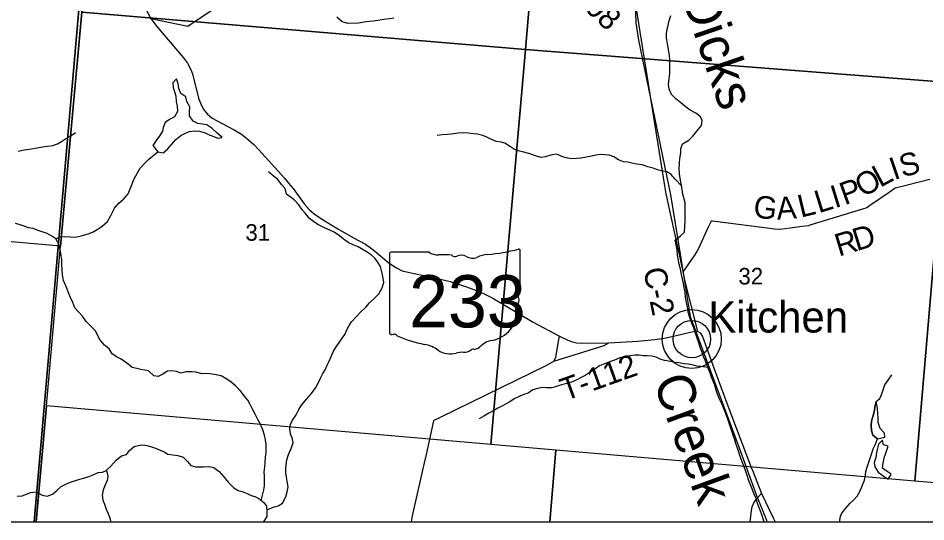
# Model space of a CAD drawing. Extents: x 0 to 42, y 0 to 22.
# Drawn here: x 4.786 to 5.931, y 14.1 to 14.736 of the extents above; entities that cross this region are included whole.
import ezdxf

# ---------------------------------------------------------------- set-up
doc = ezdxf.new("R2010")
doc.units = 0
for name, color, linetype in [('GM_X_County_Road', 7, 'Continuous'), ('GM_X_County_Road_Text', 7, 'Continuous'), ('GM_X_Major_River', 7, 'Continuous'), ('GM_X_Minor_Lake', 7, 'Continuous'), ('GM_X_Minor_River', 7, 'Continuous'), ('GM_X_Minor_River_Text', 7, 'Continuous'), ('GM_X_Rail_Line', 7, 'Continuous'), ('GM_X_Section', 7, 'Continuous'), ('GM_X_Section_Text', 7, 'Continuous'), ('GM_X_State_Location', 7, 'Continuous'), ('GM_X_State_Route', 7, 'Continuous'), ('GM_X_State_Shield', 7, 'Continuous'), ('GM_X_Township_Road', 7, 'Continuous'), ('GM_X_Township_Road_Text', 7, 'Continuous'), ('GM_X_Unincorporated', 7, 'Continuous'), ('GM_X_Unincorporated_Location', 7, 'Continuous'), ('GM_X_Unincorporated_Text', 7, 'Continuous'), ('SH_Cut_Line', 7, 'Continuous'), ('SH_Data', 7, 'Continuous')]:
    doc.layers.add(name, color=color, linetype=linetype)

msp = doc.modelspace()

# ---------------------------------------------------------------- linework, layer by layer
at = {"layer": 'GM_X_County_Road'}
for points in [[(5.6248, 14.416), (5.6235, 14.4219), (5.6031, 14.5142), (5.6015, 14.524), (5.5656, 14.7501), (5.5654, 14.7514)], [(5.6264, 14.4073), (5.6255, 14.4121), (5.6248, 14.416)], [(5.6433, 14.3404), (5.6265, 14.4068), (5.6264, 14.4073)], [(5.3009, 14.185), (5.3104, 14.2274), (5.3106, 14.2283), (5.3186, 14.2321), (5.4529, 14.2977), (5.4618, 14.3027), (5.4642, 14.3074), (5.4667, 14.323), (5.4686, 14.3345)], [(5.282, 14.1), (5.2836, 14.1074), (5.2986, 14.1746), (5.3009, 14.185)]]:
    msp.add_lwpolyline(points, dxfattribs=at)
at = {"layer": 'GM_X_Major_River'}
for points in [[(4.7848, 14.1324), (4.7912, 14.133), (4.7965, 14.1349), (4.8022, 14.1372), (4.8088, 14.1378), (4.8166, 14.1336), (4.8225, 14.1326), (4.8295, 14.1351), (4.8355, 14.1402), (4.8403, 14.1448), (4.8469, 14.148), (4.8522, 14.1501), (4.8585, 14.152), (4.864, 14.1539), (4.8702, 14.1556), (4.8753, 14.1572), (4.8814, 14.1596), (4.8871, 14.1623), (4.8924, 14.1629), (4.8971, 14.1648), (4.903, 14.1703), (4.9098, 14.1779), (4.9163, 14.1832), (4.9229, 14.1849), (4.9267, 14.19), (4.9326, 14.195), (4.9373, 14.1965), (4.9435, 14.1971), (4.9485, 14.1963), (4.9532, 14.195)], [(4.9532, 14.195), (4.9595, 14.1929), (4.9652, 14.1906), (4.9701, 14.1882), (4.975, 14.1855), (4.9813, 14.1844), (4.9875, 14.1838), (4.9942, 14.1816), (4.9997, 14.1761), (5.004, 14.1713), (5.0097, 14.1694), (5.0148, 14.1696), (5.0199, 14.1694), (5.0266, 14.1698), (5.033, 14.1687), (5.0396, 14.1634), (5.0453, 14.1567), (5.051, 14.1503), (5.058, 14.1431), (5.0635, 14.1397), (5.0688, 14.1382), (5.0749, 14.1357), (5.0798, 14.1334), (5.0846, 14.1319), (5.0895, 14.1295), (5.096, 14.1245), (5.0992, 14.1198), (5.0999, 14.1126), (5.0998, 14.1069), (5.0967, 14.1022), (5.0955, 14.1)]]:
    msp.add_lwpolyline(points, dxfattribs=at)
at = {"layer": 'GM_X_Minor_Lake'}
for points in [[(5.0155, 14.6024), (5.0125, 14.6029), (5.0067, 14.6055), (5.0021, 14.6124), (5.0023, 14.6175), (5.0025, 14.6237), (4.9987, 14.6304), (4.9974, 14.6364), (4.9912, 14.6406), (4.9887, 14.6469), (4.9878, 14.6529), (4.9859, 14.6592), (4.9811, 14.6539), (4.9817, 14.648), (4.9832, 14.6432), (4.9849, 14.6372), (4.9853, 14.6307), (4.9866, 14.6245), (4.987, 14.6177), (4.9832, 14.6112), (4.9768, 14.608), (4.9713, 14.6042), (4.9691, 14.5979), (4.9681, 14.593), (4.9647, 14.5875), (4.9602, 14.5815), (4.9561, 14.575)], [(4.9561, 14.575), (4.9621, 14.5671), (4.9689, 14.5659), (4.9744, 14.5705), (4.9799, 14.5767), (4.9851, 14.5826), (4.9914, 14.5875), (4.9963, 14.59), (5.0019, 14.5927), (5.0091, 14.5934), (5.015, 14.593), (5.022, 14.591), (5.0271, 14.5885), (5.0327, 14.5864), (5.0376, 14.5841), (5.0433, 14.5853), (5.0367, 14.5908), (5.0304, 14.597), (5.024, 14.601), (5.018, 14.602), (5.0155, 14.6024)], [(5.8679, 14.2517), (5.8662, 14.2452), (5.866, 14.2405), (5.8643, 14.2341), (5.8624, 14.2272), (5.8618, 14.2217), (5.8622, 14.2151), (5.8639, 14.2094), (5.8696, 14.2048)], [(5.8696, 14.2048), (5.8789, 14.2067), (5.8785, 14.2119), (5.873, 14.2179), (5.8705, 14.2253), (5.8707, 14.231), (5.8701, 14.2369), (5.8699, 14.2437), (5.8679, 14.2517)], [(5.8834, 14.1957), (5.8774, 14.1973), (5.876, 14.2033), (5.8711, 14.198), (5.8698, 14.1929), (5.8687, 14.1876), (5.8677, 14.1813), (5.8656, 14.1749), (5.8666, 14.1695), (5.8706, 14.1629), (5.877, 14.1582), (5.8833, 14.1538), (5.8853, 14.1571)], [(5.8853, 14.1571), (5.8871, 14.1601), (5.8821, 14.1637), (5.8762, 14.1678), (5.8768, 14.1739), (5.8781, 14.1806), (5.88, 14.1853), (5.8834, 14.1957)]]:
    msp.add_lwpolyline(points, dxfattribs=at)
at = {"layer": 'GM_X_Minor_River'}
for points in [[(5.2599, 14.7359), (5.2542, 14.7349), (5.2474, 14.734), (5.242, 14.7331), (5.2342, 14.732), (5.2289, 14.7313), (5.2223, 14.7305), (5.2153, 14.7296), (5.2017, 14.7289), (5.1945, 14.7312), (5.1879, 14.7371)], [(5.6242, 14.5134), (5.6231, 14.5226), (5.6216, 14.5288), (5.6209, 14.5339), (5.6202, 14.5392), (5.6196, 14.5457), (5.6199, 14.5525), (5.6206, 14.5588), (5.6218, 14.5658), (5.6218, 14.5707), (5.6239, 14.5769), (5.6317, 14.5817), (5.6368, 14.5866), (5.6418, 14.5932), (5.6478, 14.6002), (5.6488, 14.6064), (5.6466, 14.6112), (5.6405, 14.6157), (5.6337, 14.6195), (5.627, 14.6245), (5.6219, 14.6287), (5.6153, 14.634), (5.61, 14.6392), (5.607, 14.646), (5.6061, 14.6521), (5.6069, 14.6591), (5.6077, 14.6657), (5.6081, 14.672), (5.6081, 14.6786), (5.6078, 14.6835), (5.6074, 14.6887), (5.6067, 14.6938), (5.6054, 14.7006), (5.6045, 14.7057), (5.6037, 14.7107), (5.6036, 14.7154), (5.6041, 14.7203), (5.6059, 14.7264), (5.6065, 14.7311), (5.6091, 14.7389)], [(4.7861, 14.5679), (4.7917, 14.5692), (4.7967, 14.5699), (4.8031, 14.571), (4.8099, 14.572), (4.8167, 14.5733), (4.8235, 14.574), (4.8299, 14.5749), (4.8358, 14.577), (4.8421, 14.5807), (4.8472, 14.5841), (4.8529, 14.5877), (4.8585, 14.5916)], [(5.6227, 14.5242), (5.6147, 14.5324), (5.6092, 14.5387), (5.6043, 14.5418), (5.5994, 14.5428), (5.5937, 14.5437), (5.5869, 14.5462), (5.58, 14.5481), (5.573, 14.5505), (5.5664, 14.5514), (5.5615, 14.5522), (5.5549, 14.5541), (5.5496, 14.5545), (5.543, 14.557), (5.5373, 14.5605), (5.5316, 14.5626), (5.5258, 14.5632), (5.5209, 14.5636), (5.5145, 14.563), (5.509, 14.5617), (5.5025, 14.5601), (5.4957, 14.5591), (5.4904, 14.5588), (5.4833, 14.5581), (5.477, 14.5596), (5.4719, 14.5611), (5.4653, 14.564), (5.4591, 14.5633), (5.451, 14.5605), (5.4458, 14.5599), (5.4409, 14.5611), (5.4302, 14.5647), (5.4221, 14.5672), (5.4168, 14.5682), (5.4119, 14.5701), (5.4068, 14.5734), (5.4, 14.5779), (5.3951, 14.5791), (5.3891, 14.5799), (5.3823, 14.5828), (5.3772, 14.5854), (5.3719, 14.5877), (5.3655, 14.5891), (5.3604, 14.5899), (5.3538, 14.5905), (5.3479, 14.5911), (5.3404, 14.5905), (5.3326, 14.5892), (5.3275, 14.5887), (5.3207, 14.5885), (5.3143, 14.5878)], [(4.9247, 14.5138), (4.9272, 14.5205), (4.9297, 14.5267), (4.9326, 14.5329), (4.9364, 14.5403), (4.9398, 14.5462), (4.9451, 14.552), (4.951, 14.5577), (4.9621, 14.5671)], [(5.1244, 14.5137), (5.1228, 14.5206), (5.1184, 14.5257), (5.1134, 14.532), (5.1077, 14.5369), (5.1019, 14.5419)], [(4.8337, 14.4572), (4.8386, 14.4598), (4.845, 14.4601), (4.8522, 14.4596), (4.8579, 14.4594), (4.8657, 14.4609), (4.8704, 14.4622), (4.8755, 14.4638), (4.8807, 14.4662), (4.8856, 14.4691), (4.892, 14.4731), (4.8988, 14.479), (4.9026, 14.4858), (4.9051, 14.4907), (4.9077, 14.4959), (4.913, 14.5021), (4.9189, 14.5074), (4.9247, 14.5138)], [(5.0997, 14.1152), (5.109, 14.1189), (5.114, 14.1202), (5.1195, 14.1236), (5.1236, 14.1314), (5.1253, 14.1377), (5.1268, 14.1443), (5.1253, 14.1515), (5.1246, 14.1563), (5.1238, 14.1619), (5.1236, 14.1667), (5.124, 14.172), (5.1251, 14.1784), (5.127, 14.1851), (5.1302, 14.1925), (5.1329, 14.1999), (5.1317, 14.206), (5.1296, 14.2107), (5.1285, 14.2179), (5.1294, 14.223), (5.1321, 14.2284), (5.1368, 14.2352), (5.1402, 14.2416), (5.1435, 14.2472), (5.1503, 14.2553), (5.156, 14.2618), (5.1613, 14.2694), (5.1649, 14.276), (5.1673, 14.2813), (5.17, 14.2864), (5.1736, 14.2927), (5.1758, 14.2976), (5.1783, 14.3026), (5.1809, 14.3087), (5.1834, 14.3145), (5.187, 14.321), (5.1914, 14.3269), (5.1948, 14.3318), (5.198, 14.3366), (5.2008, 14.343), (5.2037, 14.3478), (5.2063, 14.3525), (5.2126, 14.359), (5.2181, 14.3652), (5.2247, 14.3709), (5.2292, 14.3764), (5.2355, 14.3823), (5.241, 14.388), (5.2453, 14.3952), (5.2472, 14.4019), (5.2463, 14.4074), (5.2453, 14.4138), (5.2429, 14.4222), (5.2391, 14.4282), (5.236, 14.433), (5.2311, 14.437), (5.2264, 14.4402), (5.221, 14.4434), (5.2148, 14.447), (5.2085, 14.4498), (5.2021, 14.4527), (5.196, 14.4574), (5.1913, 14.4612), (5.1845, 14.4658), (5.1793, 14.4682), (5.1723, 14.4712), (5.1649, 14.4747), (5.1602, 14.4777), (5.1536, 14.483), (5.1484, 14.4891), (5.1441, 14.4938), (5.1399, 14.5002), (5.1342, 14.5063), (5.1244, 14.5137)], [(5.6183, 14.4318), (5.6177, 14.4367), (5.617, 14.4435), (5.6158, 14.4498), (5.6145, 14.4555), (5.6215, 14.4612), (5.6264, 14.4657), (5.627, 14.4731), (5.6272, 14.4802), (5.6274, 14.4853), (5.6272, 14.4917), (5.6272, 14.5025), (5.6242, 14.5134)], [(5.0925, 14.1271), (5.0941, 14.1336), (5.0958, 14.1405), (5.0967, 14.1456), (5.0969, 14.1507), (5.0967, 14.1579), (5.0963, 14.1629), (5.0971, 14.1693), (5.0974, 14.1744), (5.098, 14.1818), (5.0988, 14.1877), (5.0989, 14.1928), (5.0989, 14.198), (5.098, 14.2035), (5.0969, 14.2094), (5.0946, 14.216), (5.0925, 14.2211), (5.0887, 14.2285), (5.0855, 14.235), (5.0821, 14.2412), (5.0781, 14.2488), (5.0756, 14.2537), (5.0716, 14.2588), (5.0659, 14.2659), (5.0601, 14.2715), (5.0546, 14.2763), (5.0494, 14.2799), (5.042, 14.2844), (5.036, 14.2856), (5.0309, 14.2865), (5.0238, 14.2871), (5.0182, 14.2867), (5.01, 14.2891), (5.0049, 14.2895), (4.9975, 14.2895), (4.9913, 14.2876), (4.9858, 14.2897), (4.9797, 14.2908), (4.9744, 14.2901), (4.9685, 14.2865), (4.9628, 14.2836), (4.9573, 14.2844), (4.9505, 14.2906), (4.9456, 14.2916), (4.9408, 14.2923), (4.9359, 14.2934), (4.93, 14.295), (4.9247, 14.2991), (4.9198, 14.3027), (4.9151, 14.3056), (4.9103, 14.3082), (4.9046, 14.312), (4.901, 14.3183), (4.895, 14.3232), (4.8887, 14.3306), (4.8857, 14.3368), (4.8832, 14.3416), (4.8718, 14.353), (4.8671, 14.3594), (4.8618, 14.3653), (4.8574, 14.37), (4.8549, 14.3767), (4.8523, 14.3831), (4.8502, 14.3884), (4.8473, 14.3949), (4.8435, 14.4047), (4.842, 14.4121), (4.8415, 14.4176), (4.8413, 14.425), (4.8411, 14.4309), (4.8405, 14.4359), (4.8397, 14.4412), (4.8382, 14.4459), (4.8369, 14.4512), (4.8337, 14.4573), (4.8285, 14.4605), (4.8227, 14.4639), (4.8102, 14.4681), (4.8052, 14.4704), (4.7992, 14.4711), (4.7935, 14.4734), (4.7874, 14.4753), (4.7827, 14.4766)], [(5.7268, 14.1), (5.7254, 14.104), (5.7233, 14.1103), (5.7208, 14.1169), (5.7186, 14.123), (5.717, 14.1285), (5.7144, 14.1349), (5.7106, 14.1448), (5.7076, 14.1518), (5.706, 14.1571), (5.7038, 14.1636), (5.7015, 14.1694), (5.6992, 14.1757), (5.6965, 14.1825), (5.6948, 14.1878), (5.6927, 14.1941), (5.691, 14.1988), (5.6897, 14.2036), (5.688, 14.2083), (5.6865, 14.2132), (5.6848, 14.2182), (5.6833, 14.2231), (5.6812, 14.2298), (5.6787, 14.2366), (5.6766, 14.2419), (5.6738, 14.248), (5.6705, 14.2548), (5.6679, 14.2612), (5.6665, 14.266), (5.6645, 14.2724), (5.6626, 14.2777), (5.6603, 14.2827), (5.6586, 14.2878), (5.6561, 14.2939), (5.654, 14.2992), (5.6523, 14.3039), (5.6502, 14.3088), (5.6487, 14.3136), (5.6462, 14.3199), (5.6443, 14.3261), (5.6419, 14.3331), (5.6398, 14.339), (5.6381, 14.3447), (5.6356, 14.3508), (5.6333, 14.358), (5.6312, 14.3646), (5.6303, 14.3714), (5.6291, 14.3768), (5.6278, 14.3832), (5.6271, 14.3897), (5.6261, 14.395), (5.625, 14.401), (5.6236, 14.4084), (5.6221, 14.4141), (5.6212, 14.4191), (5.6195, 14.4251), (5.6183, 14.4318)], [(5.6558, 14.2947), (5.647, 14.2959), (5.6421, 14.2967), (5.6362, 14.2982), (5.6311, 14.2992), (5.626, 14.2993), (5.6193, 14.3009), (5.6138, 14.301), (5.6068, 14.3029), (5.6011, 14.3035), (5.5956, 14.3054), (5.5905, 14.3077), (5.5854, 14.309), (5.5793, 14.3094), (5.5742, 14.3096), (5.5691, 14.3105), (5.5642, 14.3103), (5.5579, 14.3095), (5.5515, 14.3082), (5.5448, 14.3069), (5.538, 14.304), (5.5318, 14.3021), (5.5257, 14.2995), (5.5193, 14.2968), (5.5145, 14.2934), (5.5075, 14.289), (5.5011, 14.2848), (5.496, 14.2824), (5.4906, 14.2793), (5.484, 14.2763), (5.478, 14.2748), (5.4711, 14.2729), (5.4649, 14.271), (5.459, 14.2692), (5.4518, 14.2692), (5.4467, 14.2696), (5.4416, 14.2685), (5.4351, 14.2666), (5.4294, 14.2624), (5.4238, 14.2609), (5.4186, 14.2588), (5.4116, 14.2554), (5.4063, 14.2516), (5.4008, 14.2485), (5.3959, 14.2462), (5.391, 14.2436), (5.3859, 14.2407), (5.3798, 14.2371), (5.3732, 14.2335), (5.3675, 14.2301)], [(5.822, 14.1), (5.8221, 14.1008), (5.8228, 14.1056), (5.8243, 14.1103), (5.8293, 14.117), (5.8348, 14.1232), (5.8395, 14.1274), (5.844, 14.1323), (5.8474, 14.1384), (5.8503, 14.1456), (5.8535, 14.1528), (5.8545, 14.1589), (5.8552, 14.1637), (5.8567, 14.169), (5.8586, 14.1741), (5.8601, 14.1792), (5.862, 14.1853), (5.8645, 14.1923), (5.8673, 14.1982), (5.8696, 14.2048), (5.8639, 14.2094), (5.8622, 14.2151), (5.8618, 14.2217), (5.8624, 14.2272), (5.8643, 14.2341), (5.866, 14.2405), (5.8662, 14.2452), (5.8679, 14.2517), (5.8726, 14.2557), (5.8754, 14.2616), (5.8768, 14.2665), (5.8792, 14.273), (5.8832, 14.279), (5.8877, 14.2855)], [(4.8976, 14.1652), (4.8994, 14.1572), (4.8983, 14.1521), (4.8951, 14.1447), (4.8934, 14.1399), (4.8922, 14.1335), (4.893, 14.1272), (4.8949, 14.1223), (4.8973, 14.1162), (4.8994, 14.1113), (4.9021, 14.1039), (4.9025, 14.1)], [(4.812, 14.136), (4.8107, 14.1264), (4.8103, 14.1214), (4.8102, 14.1146), (4.8096, 14.1099), (4.8087, 14.1049), (4.8087, 14.1), (4.8087, 14.1)]]:
    msp.add_lwpolyline(points, dxfattribs=at)
at = {"layer": 'GM_X_Rail_Line'}
msp.add_lwpolyline([(5.7308, 14.1), (5.7301, 14.1018), (5.7177, 14.1327), (5.6958, 14.1931), (5.634, 14.3586), (5.6214, 14.4379), (5.6092, 14.5129), (5.569, 14.7079), (5.5656, 14.7299), (5.5645, 14.7537)], dxfattribs=at)
at = {"layer": 'GM_X_Section'}
for points in [[(4.9114, 15.2467), (5.4692, 15.2069), (5.4259, 14.6961), (4.8663, 14.7432), (4.8862, 14.965)], [(5.4692, 15.2069), (6.0007, 15.1645), (5.9598, 14.6544), (5.4259, 14.6961)], [(4.3907, 15.0059), (4.8862, 14.965), (4.8663, 14.7432), (4.8395, 14.4481), (4.3445, 14.4917)], [(4.8663, 14.7432), (5.4259, 14.6961), (5.3821, 14.1977), (4.8218, 14.2464), (4.8395, 14.4481)], [(5.4259, 14.6961), (5.9598, 14.6544), (5.9168, 14.1513), (5.4641, 14.1906), (5.3821, 14.1977)], [(5.9598, 14.6544), (6.4917, 14.6201), (6.4453, 14.1086), (5.9675, 14.1471), (5.9168, 14.1513)]]:
    msp.add_lwpolyline(points, close=True, dxfattribs=at)
at = {"layer": 'GM_X_State_Route'}
for points in [[(4.9468, 14.748), (4.9535, 14.7351), (4.9568, 14.7305), (4.9609, 14.725), (4.9945, 14.6858), (4.9997, 14.6787), (5.0031, 14.6728), (5.0058, 14.6655), (5.0134, 14.6348), (5.0168, 14.6264), (5.0202, 14.6202), (5.0248, 14.6146), (5.0309, 14.6094), (5.0496, 14.5993), (5.0587, 14.5948), (5.0676, 14.5891), (5.074, 14.5844), (5.0832, 14.5764), (5.0896, 14.5695), (5.1218, 14.5339), (5.1272, 14.5275), (5.1327, 14.5207), (5.1469, 14.5014), (5.153, 14.4941), (5.1594, 14.4886), (5.1687, 14.4825), (5.1892, 14.4697), (5.2091, 14.4583), (5.2241, 14.4504), (5.2305, 14.446), (5.2353, 14.4421), (5.2539, 14.4263), (5.2634, 14.4206), (5.2705, 14.417), (5.2794, 14.4146), (5.3117, 14.4079), (5.3311, 14.4032), (5.3514, 14.3968), (5.363, 14.3925), (5.3731, 14.3881), (5.3845, 14.3822), (5.4355, 14.3522), (5.4686, 14.3345), (5.4783, 14.3298), (5.4833, 14.3276), (5.4901, 14.3258), (5.498, 14.3254), (5.5308, 14.3261), (5.5677, 14.3281), (5.5888, 14.33), (5.6031, 14.3324), (5.6393, 14.3405), (5.6433, 14.3404), (5.6461, 14.3387), (5.649, 14.3341), (5.6656, 14.2887), (5.6798, 14.2496), (5.7106, 14.1684)], [(5.7106, 14.1684), (5.7124, 14.1638), (5.7237, 14.1359), (5.7384, 14.1051), (5.7409, 14.1)]]:
    msp.add_lwpolyline(points, dxfattribs=at)
at = {"layer": 'GM_X_State_Shield'}
for p, q in [((5.2544, 14.4385), (5.2544, 14.3384)), ((5.3042, 14.4402), (5.256, 14.4402)), ((5.4191, 14.3903), (5.4191, 14.4427)), ((5.4191, 14.3903), (5.4191, 14.3903))]:
    msp.add_line(p, q, dxfattribs=at)
for centre, major_axis, start_param, end_param in [((5.2562, 14.4387), (0.00191, 0), 1.712693, 3.28349), ((5.3157, 14.4518), (0.0185, 0), 4.042523, 4.731795), ((5.3219, 14.384), (0.0665, 0), 1.404758, 1.657858), ((5.337, 14.4392), (0.00534, 0), 3.836095, 5.185415), ((5.3448, 14.4276), (0.0111, 0), 0.950623, 2.079405), ((5.3591, 14.4435), (0.0134, 0), 4.081561, 5.145723), ((5.3827, 14.4096), (0.0352, 0), 1.699011, 2.107814), ((5.3604, 14.5766), (0.1748, 0), 4.814394, 5.042369), ((5.4173, 14.4429), (0.00183, 0), 6.141152, 7.989035), ((5.4187, 14.3865), (0.00284, 0), 1.883978, 3.671073), ((5.4172, 14.3901), (0.00196, 0), 5.05454, 6.418171), ((5.4007, 14.3799), (0.017, 0), 5.934695, 6.695948), ((5.3702, 14.3617), (0.0437, 0), 5.101752, 6.440018), ((5.4257, 14.3684), (0.0124, 0), 2.387724, 3.262537), ((5.2563, 14.3382), (0.00193, 0), 3.00124, 4.508301), ((5.2566, 14.3484), (0.0147, 0), 4.665946, 4.897461), ((5.2596, 14.3326), (0.0053, 0), 0.519207, 1.627899), ((5.3265, 14.4225), (0.1262, 0), 4.195997, 4.488961), ((5.2888, 14.2934), (0.0395, 0), 0.823519, 1.323587), ((5.3583, 14.3287), (0.0141, 0), 4.937069, 5.64225), ((5.3887, 14.3103), (0.0239, 0), 1.647645, 2.488434), ((5.3316, 14.3321), (0.0251, 0), 4.026481, 4.996735), ((5.346, 14.2975), (0.0206, 0), 1.495662, 1.94098), ((5.3479, 14.3246), (0.0133, 0), 4.691044, 5.507374), ((5.3599, 14.3149), (0.00376, 0), 1.147584, 2.315152)]:
    msp.add_ellipse(centre, major_axis=major_axis, ratio=0.8, start_param=start_param, end_param=end_param, dxfattribs=at)
at = {"layer": 'GM_X_Township_Road'}
for points in [[(2.1, 16.7767), (2.1, 14.1), (4.8064, 14.1), (4.8624, 14.7416), (4.8758, 14.903), (4.8808, 14.9641), (4.9077, 15.2247), (4.9078, 15.2254), (4.9102, 15.2488), (4.9123, 15.2667), (4.9169, 15.3007), (4.9206, 15.3383), (4.9223, 15.3554), (4.9225, 15.3576), (4.9236, 15.3654), (4.9222, 15.3761), (4.926, 15.4163), (4.9302, 15.4651), (4.9327, 15.4994), (4.9538, 15.7455), (4.9636, 15.8483), (4.9761, 15.9816)], [(4.9761, 15.9816), (4.9636, 15.8483), (4.9538, 15.7455), (4.9327, 15.4994), (4.9302, 15.4651), (4.926, 15.4163), (4.9222, 15.3761), (4.9236, 15.3654), (4.9225, 15.3576), (4.9223, 15.3554), (4.9206, 15.3383), (4.9169, 15.3007), (4.9123, 15.2667), (4.9102, 15.2488), (4.9078, 15.2254), (4.9077, 15.2247), (4.8808, 14.9641), (4.8758, 14.903), (4.8624, 14.7416), (4.8064, 14.1), (8.0502, 14.1)], [(4.9535, 14.7351), (5.0002, 14.7257), (5.0384, 14.7513), (5.0628, 14.8227), (5.1208, 14.8749)], [(5.6248, 14.416), (5.6235, 14.4219), (5.6031, 14.5142), (5.6015, 14.524), (5.5656, 14.7501), (5.5654, 14.7514)], [(5.9359, 14.532), (5.8925, 14.5212), (5.8922, 14.5211), (5.8843, 14.5157), (5.8598, 14.4988), (5.8563, 14.4964), (5.8509, 14.4948), (5.7846, 14.4743), (5.7829, 14.4738), (5.7748, 14.4727), (5.7502, 14.4694), (5.7463, 14.4689), (5.7404, 14.4696), (5.6616, 14.4793), (5.6599, 14.4795), (5.6564, 14.4721), (5.6439, 14.4451), (5.6421, 14.4413), (5.6389, 14.4366), (5.6277, 14.4202), (5.6248, 14.416)], [(5.4618, 14.3027), (5.5251, 14.3224), (5.5308, 14.3261)], [(5.7093, 14.1), (5.711, 14.1144), (5.7116, 14.1191), (5.7139, 14.1239), (5.7175, 14.1295), (5.7237, 14.1359)]]:
    msp.add_lwpolyline(points, dxfattribs=at)
at = {"layer": 'GM_X_Unincorporated'}
for points in [[(4.3088, 14.1), (4.8087, 14.1), (4.8218, 14.2464), (4.8395, 14.4481), (4.3445, 14.4917)], [(4.8087, 14.1), (5.4565, 14.1), (5.4641, 14.1906), (5.3821, 14.1977), (4.8218, 14.2464)], [(5.4565, 14.1), (5.9635, 14.1), (5.9675, 14.1471), (5.9168, 14.1513), (5.4641, 14.1906)]]:
    msp.add_lwpolyline(points, close=True, dxfattribs=at)
for radius in [0.0372, 0.0236]:
    msp.add_circle((5.6356, 14.3307), radius, dxfattribs=at)
at = {"layer": 'GM_X_Unincorporated_Location'}
msp.add_line((5.6356, 14.3307), (5.6356, 14.3307), dxfattribs=at)
at = {"layer": 'SH_Cut_Line'}
msp.add_lwpolyline([(2.1, 20.9), (2.1, 14.1), (8.0502, 14.1), (8.0687, 14.307), (8.0834, 14.5136), (8.1512, 15.2413), (8.1576, 15.3191), (8.1628, 15.379), (8.1684, 15.4461), (8.1694, 15.4594), (8.1698, 15.4663), (8.1723, 15.4906), (8.2423, 16.3206)], dxfattribs=at)
at = {"layer": 'SH_Data'}
msp.add_line((2.1, 14.1), (8.9, 14.1), dxfattribs=at)

# ---------------------------------------------------------------- texts
at = {"layer": 'GM_X_County_Road_Text'}
msp.add_text('C-2', height=0.02841, rotation=281.6542, dxfattribs=at).set_placement((5.5742, 14.4184))
at = {"layer": 'GM_X_Minor_River_Text'}
for s, rotation, p in [('Dicks', 288.9983, (5.622, 14.7629)), ('Creek', 289.9984, (5.5865, 14.2774))]:
    msp.add_text(s, height=0.04735, rotation=rotation, dxfattribs=at).set_placement(p)
at = {"layer": 'GM_X_Section_Text'}
for s, p in [('31', (5.0727, 14.4548)), ('32', (5.6944, 14.3996))]:
    msp.add_text(s, height=0.02093, rotation=0, dxfattribs=at).set_placement(p)
at = {"layer": 'GM_X_State_Location'}
for s in ['s', 'r']:
    msp.add_text(s, height=0.0000947, dxfattribs=at).set_placement((5.3349, 14.3818))
msp.add_text('233', height=0.0000947, rotation=0, dxfattribs=at).set_placement((5.3015, 14.3749))
at = {"layer": 'GM_X_State_Shield'}
msp.add_text('233', height=0.06592, dxfattribs=at).set_placement((5.2791, 14.3454))
at = {"layer": 'GM_X_Township_Road_Text'}
for s, height, rotation, p in [('T-108', 0.02841, 316.591, (5.4576, 14.7864)), ('I', 0.0284, 18.8546, (5.8907, 14.5311)), ('S', 0.0284, 14.4004, (5.9011, 14.5347)), ('L', 0.0284, 28.3861, (5.8731, 14.5215)), ('O', 0.0284, 31.3706, (5.8521, 14.5087)), ('P', 0.0284, 19.6577, (5.8283, 14.4995)), ('L', 0.0284, 17.1545, (5.7956, 14.4894)), ('I', 0.0284, 17.0821, (5.8159, 14.4957)), ('G', 0.0284, 352.6653, (5.7121, 14.4846)), ('A', 0.0284, 4.4151, (5.7432, 14.4812)), ('L', 0.0284, 13.4921, (5.773, 14.4839)), ('D', 0.0284, 17.1433, (5.8435, 14.4415)), ('R', 0.0284, 16.808, (5.821, 14.4347)), ('T-112', 0.02841, 19.6754, (5.4759, 14.2524))]:
    msp.add_text(s, height=height, rotation=rotation, dxfattribs=at).set_placement(p)
at = {"layer": 'GM_X_Unincorporated_Text'}
msp.add_text('Kitchen', height=0.03949, rotation=0, dxfattribs=at).set_placement((5.6565, 14.3389))

doc.saveas('drawing.dxf')
